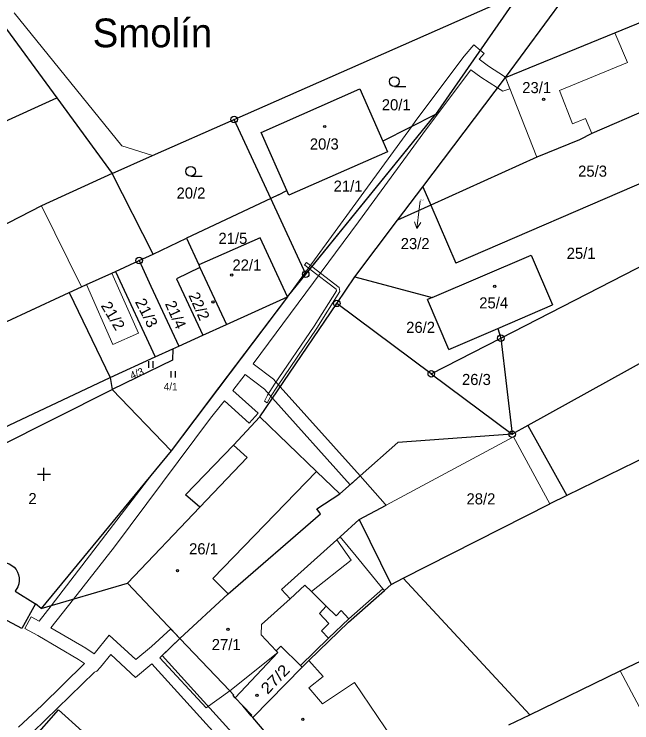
# Model space of a CAD drawing. Extents: x -606517 to -602431, y -1183120 to -1179397.
# Drawn here: x -605420.9 to -605326.3, y -1180870.1 to -1180761.6 of the extents above; entities that cross this region are included whole.
import ezdxf
from ezdxf.enums import TextEntityAlignment as Align

# ---------------------------------------------------------------- set-up
doc = ezdxf.new("R2010")
doc.units = 0
doc.header["$LTSCALE"] = 0.68
for name, color, linetype, lineweight in [('1', 7, 'Continuous', 25), ('13', 7, 'Continuous', 13), ('3', 7, 'Continuous', 25), ('4', 7, 'Continuous', 13), ('5', 7, 'Continuous', 25), ('7', 7, 'Continuous', 13), ('8', 7, 'Continuous', 25)]:
    doc.layers.add(name, color=color, linetype=linetype, lineweight=lineweight)
doc.layers.add('2', color=7, linetype='Continuous')

msp = doc.modelspace()

# ---------------------------------------------------------------- linework, layer by layer
at = {"layer": '1'}
for p, q in [((-605345.64, -1180771.32), (-605326.18, -1180744.86)), ((-605387.19, -1180777.73), (-605343.44, -1180758.42)), ((-605343.44, -1180758.42), (-605356.33, -1180776.94)), ((-605423.26, -1180762.37), (-605414.36, -1180774.43)), ((-605328.85, -1180764.46), (-605324.37, -1180762.62)), ((-605345.64, -1180771.32), (-605328.85, -1180764.46)), ((-605358.29, -1180788.05), (-605345.64, -1180771.32)), ((-605383.04, -1180779.7), (-605367.95, -1180773.04)), ((-605367.95, -1180773.04), (-605364.39, -1180781.06)), ((-605445.31, -1180788.34), (-605414.36, -1180774.43)), ((-605414.36, -1180774.43), (-605405.89, -1180785.98)), ((-605320.02, -1180774.54), (-605332.37, -1180779.85)), ((-605376.22, -1180801.4), (-605356.33, -1180776.94)), ((-605356.33, -1180776.94), (-605364.39, -1180781.06)), ((-605399.69, -1180783.24), (-605387.19, -1180777.73)), ((-605381.59, -1180789.81), (-605387.19, -1180777.73)), ((-605379.11, -1180788.59), (-605383.04, -1180779.7)), ((-605307.75, -1180780.1), (-605353.24, -1180799.73)), ((-605332.37, -1180779.85), (-605334.3, -1180780.85)), ((-605364.39, -1180781.06), (-605363.69, -1180782.65)), ((-605334.3, -1180780.85), (-605340.8, -1180783.47)), ((-605363.69, -1180782.65), (-605378.79, -1180789.32)), ((-605340.8, -1180783.47), (-605357.08, -1180790.85)), ((-605405.89, -1180785.98), (-605416.71, -1180790.96)), ((-605362.14, -1180793.15), (-605358.29, -1180788.05)), ((-605358.29, -1180788.05), (-605357.08, -1180790.85)), ((-605380.4, -1180789.25), (-605381.59, -1180789.81)), ((-605380.4, -1180789.25), (-605379.11, -1180788.59)), ((-605378.79, -1180789.32), (-605379.11, -1180788.59)), ((-605346.34, -1180811.21), (-605303.67, -1180789.29)), ((-605376.22, -1180801.4), (-605381.59, -1180789.81)), ((-605416.71, -1180790.96), (-605429.75, -1180797.61)), ((-605357.08, -1180790.85), (-605362.14, -1180793.15)), ((-605357.08, -1180790.85), (-605353.24, -1180799.73)), ((-605368.71, -1180801.8), (-605362.14, -1180793.15)), ((-605399.61, -1180798.33), (-605394.5, -1180795.91)), ((-605383.21, -1180795.83), (-605392.61, -1180799.99)), ((-605379.03, -1180804.85), (-605383.21, -1180795.83)), ((-605401.74, -1180799.31), (-605399.61, -1180798.33)), ((-605356.85, -1180804.99), (-605341.67, -1180798.48)), ((-605341.67, -1180798.48), (-605338.4, -1180806.1)), ((-605405.38, -1180800.97), (-605401.74, -1180799.31)), ((-605401.74, -1180799.31), (-605399.93, -1180803.23)), ((-605392.61, -1180799.99), (-605392.42, -1180800.39)), ((-605409.8, -1180802.99), (-605405.95, -1180801.23)), ((-605405.95, -1180801.23), (-605405.38, -1180800.97)), ((-605405.38, -1180800.97), (-605399.28, -1180814.07)), ((-605392.42, -1180800.39), (-605396.02, -1180802.13)), ((-605392.42, -1180800.39), (-605388.38, -1180809.11)), ((-605379.03, -1180804.85), (-605376.22, -1180801.4)), ((-605299.09, -1180800.63), (-605342.2, -1180824.58)), ((-605396.02, -1180802.13), (-605392, -1180810.76)), ((-605371.47, -1180805.87), (-605368.71, -1180801.8)), ((-605368.71, -1180801.8), (-605356.85, -1180804.99)), ((-605412.45, -1180804.22), (-605410.57, -1180803.34)), ((-605410.57, -1180803.34), (-605409.8, -1180802.99)), ((-605399.93, -1180803.23), (-605395.68, -1180812.4)), ((-605423.96, -1180809.53), (-605412.45, -1180804.22)), ((-605412.45, -1180804.22), (-605406.17, -1180817.2)), ((-605379.03, -1180804.85), (-605396.82, -1180828.43)), ((-605388.38, -1180809.11), (-605379.03, -1180804.85)), ((-605356.85, -1180804.99), (-605357.55, -1180805.29)), ((-605354.29, -1180812.93), (-605357.55, -1180805.29)), ((-605383.24, -1180823.23), (-605371.47, -1180805.87)), ((-605356.98, -1180816.67), (-605371.47, -1180805.87)), ((-605346.81, -1180809.72), (-605338.4, -1180806.1)), ((-605392, -1180810.76), (-605388.38, -1180809.11)), ((-605354.29, -1180812.93), (-605346.81, -1180809.72)), ((-605346.81, -1180809.72), (-605346.34, -1180811.21)), ((-605395.68, -1180812.4), (-605392, -1180810.76)), ((-605356.98, -1180816.67), (-605346.34, -1180811.21)), ((-605346.34, -1180811.21), (-605344.59, -1180825.91)), ((-605396.59, -1180812.82), (-605396.62, -1180814.55)), ((-605396.59, -1180812.82), (-605395.68, -1180812.4)), ((-605293.12, -1180814.25), (-605336.22, -1180835.26)), ((-605396.62, -1180814.55), (-605405.86, -1180819.07)), ((-605436.52, -1180831.49), (-605406.17, -1180817.2)), ((-605406.17, -1180817.2), (-605405.86, -1180819.07)), ((-605356.98, -1180816.67), (-605344.59, -1180825.91)), ((-605438.49, -1180835.36), (-605405.86, -1180819.07)), ((-605405.86, -1180819.07), (-605396.82, -1180828.43)), ((-605387.28, -1180827.56), (-605383.24, -1180823.23)), ((-605342.2, -1180824.58), (-605344.59, -1180825.91)), ((-605342.2, -1180824.58), (-605336.22, -1180835.26)), ((-605344.59, -1180825.91), (-605362.11, -1180827.16)), ((-605362.11, -1180827.16), (-605367.88, -1180832.28)), ((-605396.82, -1180828.43), (-605416.73, -1180852.59)), ((-605394.64, -1180835.2), (-605387.28, -1180827.56)), ((-605367.88, -1180832.28), (-605371, -1180835.05)), ((-605364.07, -1180836.59), (-605367.88, -1180832.28)), ((-605374.52, -1180837.3), (-605371, -1180835.05)), ((-605392.42, -1180837.05), (-605394.64, -1180835.2)), ((-605336.22, -1180835.26), (-605338.84, -1180836.54)), ((-605403.52, -1180848.7), (-605392.42, -1180837.05)), ((-605368.01, -1180838.96), (-605363.91, -1180836.76)), ((-605363.91, -1180836.76), (-605364.07, -1180836.59)), ((-605361.29, -1180847.96), (-605338.84, -1180836.54)), ((-605388.11, -1180850.34), (-605373.96, -1180838.07)), ((-605374.1, -1180837.88), (-605374.52, -1180837.3)), ((-605373.96, -1180838.07), (-605374.1, -1180837.88)), ((-605368.01, -1180838.96), (-605363.15, -1180848.91)), ((-605328.07, -1180862.14), (-605282.51, -1180840.21)), ((-605363.15, -1180848.91), (-605361.29, -1180847.96)), ((-605361.29, -1180847.96), (-605341.88, -1180868.85)), ((-605416.73, -1180852.59), (-605403.52, -1180848.7)), ((-605395.52, -1180857.15), (-605403.52, -1180848.7)), ((-605364.17, -1180849.81), (-605363.15, -1180848.91)), ((-605420.31, -1180849.26), (-605420.72, -1180849.93)), ((-605420.72, -1180849.93), (-605417.63, -1180851.84)), ((-605369.65, -1180854.65), (-605364.17, -1180849.81)), ((-605395.52, -1180857.15), (-605388.11, -1180850.34)), ((-605417.63, -1180851.84), (-605419.72, -1180855.62)), ((-605416.73, -1180852.59), (-605417.63, -1180851.84)), ((-605419.72, -1180855.62), (-605422.7, -1180854.04)), ((-605369.65, -1180854.65), (-605375.77, -1180860.56)), ((-605387.85, -1180865.16), (-605395.52, -1180857.15)), ((-605380.75, -1180859.05), (-605380.01, -1180858.36)), ((-605380.01, -1180858.36), (-605377, -1180861.32)), ((-605387.04, -1180866.24), (-605380.51, -1180859.31)), ((-605380.51, -1180859.31), (-605380.75, -1180859.05)), ((-605376.75, -1180861.56), (-605375.77, -1180860.56)), ((-605384.31, -1180869.29), (-605376.75, -1180861.56)), ((-605377, -1180861.32), (-605376.75, -1180861.56)), ((-605341.88, -1180868.85), (-605328.07, -1180862.14)), ((-605387.26, -1180865.84), (-605387.85, -1180865.16)), ((-605387.34, -1180865.92), (-605387.26, -1180865.84)), ((-605387.04, -1180866.24), (-605387.34, -1180865.92)), ((-605385.84, -1180867.5), (-605387.04, -1180866.24)), ((-605384.57, -1180868.99), (-605385.84, -1180867.5)), ((-605420.88, -1180875.72), (-605414.08, -1180868.1)), ((-605414.08, -1180868.1), (-605410.46, -1180871.34)), ((-605384.31, -1180869.29), (-605384.57, -1180868.99)), ((-605376.47, -1180878.34), (-605384.31, -1180869.29)), ((-605345.08, -1180870.41), (-605341.88, -1180868.85))]:
    msp.add_line(p, q, dxfattribs=at)
for points in [[(-605399.61, -1180798.33), (-605405.89, -1180785.98), (-605399.69, -1180783.24)], [(-605381.59, -1180789.81), (-605394.5, -1180795.91), (-605392.61, -1180799.99)], [(-605406.17, -1180817.2), (-605399.28, -1180814.07), (-605396.59, -1180812.82)], [(-605424.98, -1180846.58), (-605424.673, -1180846.235), (-605424.311, -1180845.948), (-605423.907, -1180845.726), (-605423.47, -1180845.576), (-605423.014, -1180845.502), (-605422.552, -1180845.507), (-605422.098, -1180845.589), (-605421.665, -1180845.748), (-605421.264, -1180845.978), (-605420.909, -1180846.272), (-605420.608, -1180846.623), (-605420.371, -1180847.019), (-605420.205, -1180847.45), (-605420.114, -1180847.902), (-605420.102, -1180848.364), (-605420.168, -1180848.821), (-605420.31, -1180849.26)]]:
    msp.add_lwpolyline(points, dxfattribs=at)
at = {"layer": '13'}
for points in [[(-605350.48, -1180766.3), (-605351.93, -1180768.04), (-605359.34, -1180777.89), (-605360.03, -1180778.83), (-605356.33, -1180776.94), (-605379.03, -1180804.85), (-605389.51, -1180818.75), (-605396.82, -1180828.43), (-605399.82, -1180832.07), (-605415.22, -1180852.15), (-605417.07, -1180854.51), (-605418.27, -1180853.86), (-605419.25, -1180855.66), (-605417.28, -1180856.73), (-605411.03, -1180860.39), (-605410.11, -1180861.02), (-605416.63, -1180867.41), (-605420.2, -1180870.74)], [(-605386.04, -1180873.19), (-605398.21, -1180859.78), (-605395.52, -1180857.15), (-605396.89, -1180855.7), (-605399.84, -1180858.39), (-605402.25, -1180860.4), (-605406.32, -1180856.64), (-605408.65, -1180859.52), (-605409.93, -1180858.65), (-605415.25, -1180855.54), (-605411.81, -1180851.14), (-605405.53, -1180843.12), (-605390.79, -1180823.46), (-605389.13, -1180821.33), (-605388.67, -1180820.81), (-605384.89, -1180824.21), (-605383.53, -1180822.69), (-605387.38, -1180819.23), (-605385.52, -1180816.75), (-605382.55, -1180818.98), (-605381.3, -1180820.37), (-605369.42, -1180833.65), (-605367.88, -1180832.28), (-605380.12, -1180818.63), (-605381.17, -1180817.46), (-605384.29, -1180815.12), (-605368.16, -1180793.41), (-605357.7, -1180779.13), (-605350.91, -1180770.12), (-605349.4, -1180771.26), (-605346.82, -1180772.88), (-605345.64, -1180771.32), (-605345.77, -1180771.13), (-605348.22, -1180769.58), (-605349.65, -1180768.51), (-605348.9, -1180767.62), (-605349.5, -1180767.12), (-605350.48, -1180766.3)], [(-605418.03, -1180871.53), (-605408.59, -1180862.33), (-605408.23, -1180862.16), (-605407.65, -1180861.55), (-605406.1, -1180859.64), (-605402.31, -1180863.14), (-605399.82, -1180861.06), (-605387.56, -1180874.59)]]:
    msp.add_lwpolyline(points, dxfattribs=at)
for points in [[(-605346.03, -1180773.37), (-605344.97, -1180773.01), (-605345.64, -1180771.32), (-605346.82, -1180772.88)], [(-605379.03, -1180804.85), (-605356.33, -1180776.94), (-605360.03, -1180778.83)], [(-605381.64, -1180820.19), (-605380.57, -1180818.53), (-605374.53, -1180809.65), (-605371.02, -1180804.06), (-605371.09, -1180803.43), (-605375.27, -1180800.24), (-605375.59, -1180800.63), (-605371.57, -1180803.69), (-605371.53, -1180803.94), (-605374.95, -1180809.38), (-605380.99, -1180818.25), (-605382.08, -1180819.93), (-605382.55, -1180820.86), (-605382.11, -1180821.09)], [(-605375.59, -1180800.63), (-605375.27, -1180800.24), (-605376.08, -1180799.63), (-605376.43, -1180799.98)]]:
    msp.add_lwpolyline(points, close=True, dxfattribs=at)
at = {"layer": '3'}
for p, q in [((-605362.643, -1180772.67), (-605360.893, -1180772.67)), ((-605393.843, -1180786.42), (-605392.093, -1180786.42)), ((-605400.262, -1180815.74), (-605400.262, -1180814.735)), ((-605399.592, -1180815.74), (-605399.592, -1180814.735)), ((-605396.822, -1180817.24), (-605396.822, -1180816.235)), ((-605396.152, -1180817.24), (-605396.152, -1180816.235)), ((-605416.32, -1180833.06), (-605416.32, -1180831.06)), ((-605415.319, -1180832.061), (-605417.321, -1180832.061))]:
    msp.add_line(p, q, dxfattribs=at)
for centre in [(-605362.6429, -1180771.9198), (-605393.8429, -1180785.6698)]:
    msp.add_circle(centre, 0.75, dxfattribs=at)
at = {"layer": '4'}
for p, q in [((-605420.9, -1180761.38), (-605404.39, -1180781.77)), ((-605328.85, -1180764.46), (-605326.9, -1180768.99)), ((-605326.9, -1180768.99), (-605337.32, -1180773.27)), ((-605340.8, -1180783.47), (-605345.64, -1180771.32)), ((-605337.32, -1180773.27), (-605335.33, -1180778.4)), ((-605335.33, -1180778.4), (-605333.36, -1180777.55)), ((-605333.36, -1180777.55), (-605332.37, -1180779.85)), ((-605399.69, -1180783.24), (-605404.39, -1180781.77)), ((-605416.71, -1180790.96), (-605410.57, -1180803.34)), ((-605405.95, -1180801.23), (-605401.84, -1180810.44)), ((-605405.76, -1180812.16), (-605409.8, -1180802.99)), ((-605401.84, -1180810.44), (-605405.76, -1180812.16)), ((-605383.24, -1180823.23), (-605374.59, -1180831.62)), ((-605363.91, -1180836.76), (-605344.4, -1180826.3)), ((-605344.4, -1180826.3), (-605338.84, -1180836.54)), ((-605385.2, -1180829.46), (-605387.28, -1180827.56)), ((-605392.42, -1180837.05), (-605385.2, -1180829.46)), ((-605390.44, -1180847.99), (-605374.59, -1180831.62)), ((-605374.59, -1180831.62), (-605371, -1180835.05)), ((-605370.93, -1180841.59), (-605368.01, -1180838.96)), ((-605379.91, -1180849.68), (-605371.45, -1180842.06)), ((-605371.45, -1180842.06), (-605370.93, -1180841.59)), ((-605369.27, -1180845.19), (-605371.45, -1180842.06)), ((-605370.93, -1180841.59), (-605368.48, -1180844.57)), ((-605368.48, -1180844.57), (-605364.4, -1180849.55)), ((-605375.36, -1180849.99), (-605369.27, -1180845.19)), ((-605388.11, -1180850.34), (-605390.44, -1180847.99)), ((-605378.63, -1180851.09), (-605376.35, -1180849.02)), ((-605376.35, -1180849.02), (-605375.36, -1180849.99)), ((-605378.63, -1180851.09), (-605379.91, -1180849.68)), ((-605375.36, -1180849.99), (-605373.11, -1180852.2)), ((-605369.6, -1180854.15), (-605364.4, -1180849.55)), ((-605364.4, -1180849.55), (-605364.17, -1180849.81)), ((-605374.13, -1180853.36), (-605373.11, -1180852.2)), ((-605373.11, -1180852.2), (-605371.58, -1180853.7)), ((-605372.68, -1180854.85), (-605374.13, -1180853.36)), ((-605371.58, -1180853.7), (-605370.81, -1180852.88)), ((-605370.81, -1180852.88), (-605369.6, -1180854.15)), ((-605369.6, -1180854.15), (-605372.71, -1180857.12)), ((-605373.78, -1180856.01), (-605372.68, -1180854.85)), ((-605380.75, -1180859.05), (-605383.05, -1180856.6)), ((-605372.71, -1180857.12), (-605373.78, -1180856.01)), ((-605395.52, -1180857.15), (-605398.58, -1180860.15)), ((-605377, -1180861.32), (-605372.71, -1180857.12)), ((-605387.85, -1180865.16), (-605380.51, -1180859.31)), ((-605398.58, -1180860.15), (-605391.45, -1180867.78)), ((-605375.77, -1180860.56), (-605373.57, -1180862.99)), ((-605328.07, -1180862.14), (-605322.81, -1180871.99)), ((-605373.57, -1180862.99), (-605375.76, -1180864.73)), ((-605373.63, -1180867.15), (-605368.76, -1180863.92)), ((-605368.76, -1180863.92), (-605359.28, -1180877.86)), ((-605391.45, -1180867.78), (-605387.85, -1180865.16)), ((-605375.76, -1180864.73), (-605373.63, -1180867.15)), ((-605384.5, -1180868.92), (-605385.84, -1180867.5)), ((-605384.57, -1180868.99), (-605384.5, -1180868.92))]:
    msp.add_line(p, q, dxfattribs=at)
msp.add_lwpolyline([(-605383.05, -1180856.6), (-605382.99, -1180855.05), (-605378.63, -1180851.09)], dxfattribs=at)
at = {"layer": '5'}
for centre in [(-605339.7768, -1180774.6392), (-605373.3068, -1180778.7992), (-605387.5468, -1180801.5492), (-605347.2568, -1180803.2792), (-605390.442, -1180805.6434), (-605395.8668, -1180846.7892), (-605388.1368, -1180855.7692), (-605383.6968, -1180865.8792), (-605376.6668, -1180869.5292)]:
    msp.add_circle(centre, 0.175, dxfattribs=at)
at = {"layer": '7'}
msp.add_line((-605359.206, -1180794.429), (-605358.587, -1180793.496), dxfattribs=at)
msp.add_lwpolyline([(-605358.68, -1180790.16), (-605358.84, -1180791.45), (-605359.206, -1180794.429), (-605359.581, -1180793.374)], dxfattribs=at)
at = {"layer": '8'}
for centre, radius in [((-605387.19, -1180777.7299), 0.5), ((-605387.19, -1180777.7299), 0.0303), ((-605401.74, -1180799.3099), 0.5), ((-605401.74, -1180799.3099), 0.0303), ((-605376.22, -1180801.3999), 0.5), ((-605376.22, -1180801.3999), 0.0303), ((-605371.47, -1180805.8699), 0.5), ((-605371.47, -1180805.8699), 0.0303), ((-605346.34, -1180811.2099), 0.5), ((-605346.34, -1180811.2099), 0.0303), ((-605356.98, -1180816.6699), 0.5), ((-605356.98, -1180816.6699), 0.0303), ((-605344.59, -1180825.9099), 0.5), ((-605344.59, -1180825.9099), 0.0303)]:
    msp.add_circle(centre, radius, dxfattribs=at)

# ---------------------------------------------------------------- texts
at = {"layer": '2'}
for s, height, p in [('23/1', 1.7, (-605340.839, -1180773.692)), ('25/3', 1.7, (-605332.279, -1180786.482)), ('23/2', 1.7, (-605359.459, -1180797.572)), ('25/1', 1.7, (-605334.029, -1180799.055)), ('22/1', 1.7, (-605385.239, -1180800.852)), ('26/2', 1.7, (-605358.619, -1180810.392)), ('26/3', 1.7, (-605350.069, -1180818.372)), ('4/1', 1.14, (-605396.909, -1180819.18)), ('26/1', 1.7, (-605391.879, -1180844.292))]:
    msp.add_text(s, height=height, dxfattribs=at).set_placement(p, align=Align.CENTER)
for s, height, p in [('20/1', 1.7, (-605364.57, -1180776.325)), ('20/3', 1.7, (-605375.59, -1180782.325)), ('21/1', 1.7, (-605371.95, -1180788.775)), ('20/2', 1.7, (-605396.01, -1180789.835)), ('23/2', 0.2, (-605358.68, -1180790.21)), ('21/5', 1.7, (-605389.59, -1180796.765)), ('25/4', 1.7, (-605349.64, -1180806.645)), ('2', 1.7, (-605418.71, -1180836.605)), ('28/2', 1.7, (-605351.59, -1180836.645)), ('27/1', 1.7, (-605390.62, -1180858.955))]:
    msp.add_text(s, height=height, dxfattribs=at).set_placement(p)
for s, height, rotation, p in [('22/2', 1.7, 294, (-605393.3234, -1180806.6473)), ('21/4', 1.7, 294, (-605396.9234, -1180807.9473)), ('4/3', 1.139, 23, (-605401.8705, -1180817.1227))]:
    msp.add_text(s, height=height, rotation=rotation, dxfattribs=at).set_placement(p, align=Align.CENTER)
for s, rotation, width, p in [('21/2', 301, 1.05, (-605407.664, -1180806.218)), ('21/3', 297, 1.05, (-605402.418, -1180805.632)), ('27/2', 46, 1.15, (-605382.064, -1180865.805))]:
    msp.add_text(s, height=1.7, rotation=rotation, dxfattribs=dict(at, width=width)).set_placement(p)
at = {"layer": '7'}
msp.add_text('Smolín', height=4.4, dxfattribs=at).set_placement((-605408.86, -1180766.67))

doc.saveas('drawing.dxf')
